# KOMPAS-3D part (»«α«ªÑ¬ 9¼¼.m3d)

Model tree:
1. Эскиз:1
2. Операция выдавливания:1
     Расстояние 1 = 8
3. Эскиз:2
4. Операция выдавливания:2
     Расстояние 1 = 1
5. Эскиз:3
6. Операция выдавливания:3
     Расстояние 1 = 2.5; Угол 1 = 8
7. Эскиз:4
8. Вырезать элемент выдавливания:1
     Расстояние 1 = 20
9. Эскиз:5
10. Вырезать элемент выдавливания:2
     Расстояние 1 = 3; Угол 1 = 19
11. Скругление:1
     Радиус = 1
12. Скругление:2
     Радиус = 1
13. Скругление:3
     Радиус = 1
14. Эскиз:6
15. Эскиз:7
16. Вырезать элемент выдавливания:3
     Расстояние 2 = 30; Расстояние 1 = 60
17. Эскиз:8
18. Вырезать элемент выдавливания:4
     Расстояние 2 = 30; Расстояние 1 = 60
19. Эскиз:9
20. Операция выдавливания:4
     Расстояние 1 = 10; Расстояние 2 = 62
21. Эскиз:10
22. Вырезать элемент выдавливания:5
     Расстояние 2 = 30; Расстояние 1 = 60
23. Скругление:4
     Радиус = 2
24. Скругление:5
     Радиус = 2
25. Эскиз:11
26. Вырезать элемент выдавливания:6
     Расстояние 1 = 10
27. Эскиз:12
28. Вырезать элемент выдавливания:7
     Расстояние 1 = 2.5; Угол 1 = 3
29. Эскиз:13
30. Вырезать элемент выдавливания:8
     Расстояние 2 = 40; Расстояние 1 = 30
31. Эскиз:14
32. Операция выдавливания:5
     Расстояние 1 = 10
33. Операция выдавливания:6
     Расстояние 1 = 2.5; Расстояние 2 = 5.94316
34. Эскиз:15
35. Вырезать элемент выдавливания:9
     Расстояние 1 = 20
36. Эскиз:16
37. Вырезать элемент выдавливания:10
     Расстояние 1 = 10
38. Операция выдавливания:7
     Расстояние 1 = 2
39. Операция выдавливания:8
     Расстояние 1 = 0.4
40. Операция выдавливания:9
     Расстояние 1 = 0.4
